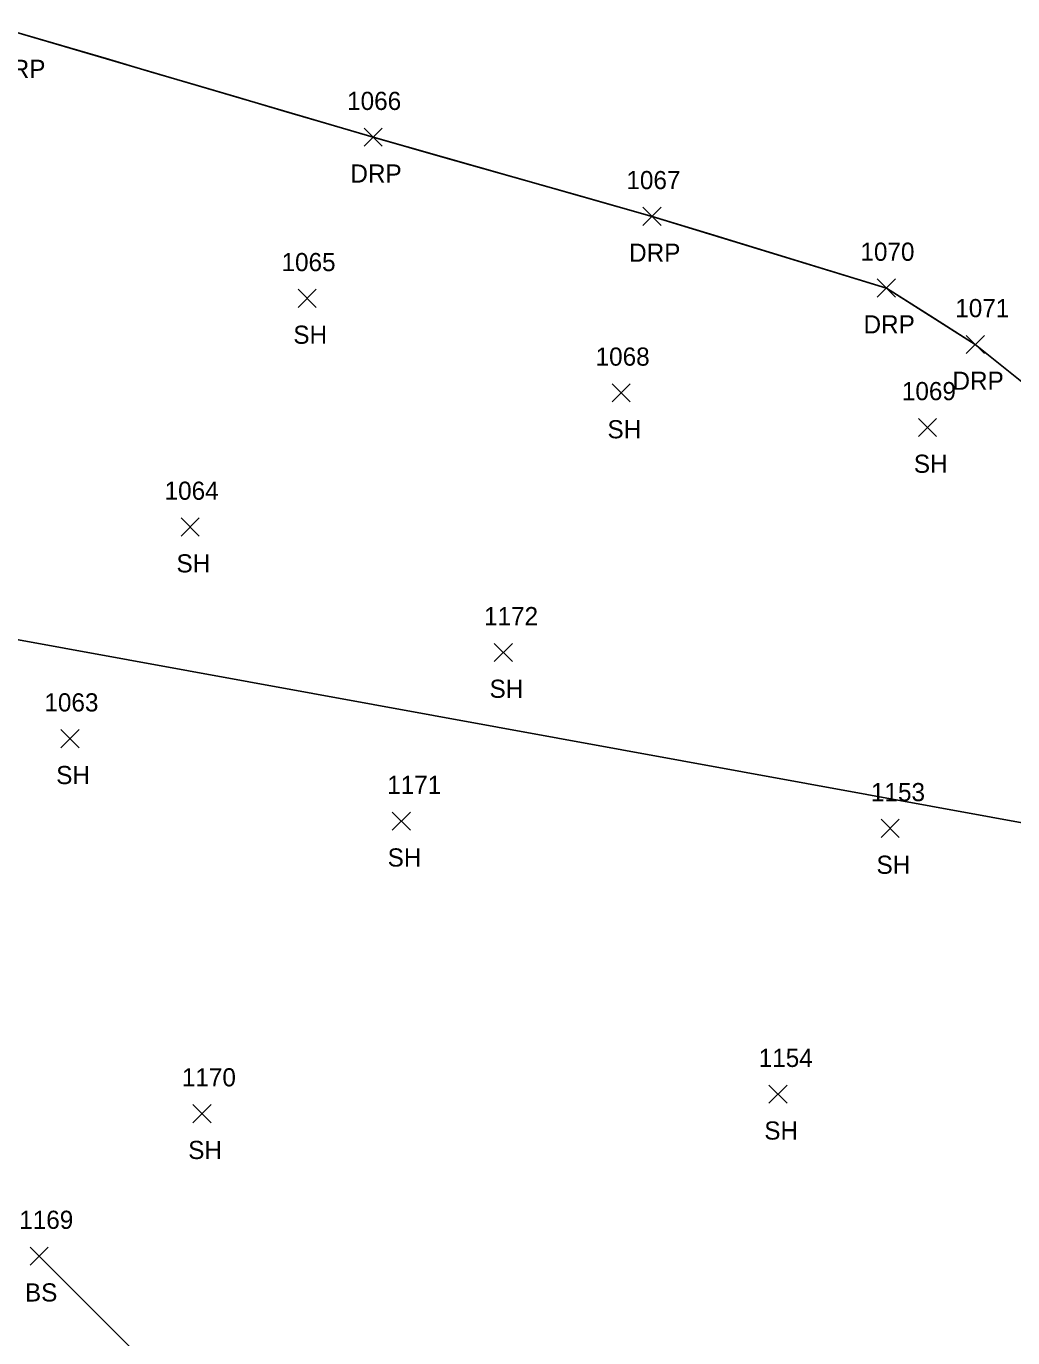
# Model space of a CAD drawing. Extents: x 1639430 to 1640195, y 612006 to 612917.
# Drawn here: x 1639980.2 to 1640088.8, y 612501.1 to 612645.5 of the extents above; entities that cross this region are included whole.
import ezdxf

# ---------------------------------------------------------------- set-up
doc = ezdxf.new("R2010")
doc.units = 0
for name, color, linetype in [('DCP', 7, 'Continuous'), ('L_A', 7, 'Continuous'), ('L_I', 7, 'Continuous'), ('L_TIC', 7, 'Continuous'), ('LELB', 7, 'Continuous'), ('LSOGP', 7, 'Continuous'), ('R_A', 7, 'Continuous'), ('R_I', 7, 'Continuous'), ('R_TIC', 7, 'Continuous'), ('RDP', 7, 'Continuous')]:
    doc.layers.add(name, color=color, linetype=linetype)

msp = doc.modelspace()

# ---------------------------------------------------------------- linework, layer by layer
at = {"layer": 'DCP'}
msp.add_lwpolyline([(1639875.64, 612596.85), (1640140.73, 612548.53)], dxfattribs=at)
at = {"layer": 'L_TIC'}
for points in [[(1640010.11, 612614.56), (1640012.11, 612616.56)], [(1640012.11, 612614.56), (1640010.11, 612616.56)], [(1640044.68, 612604.15), (1640046.68, 612606.15)], [(1640046.68, 612604.15), (1640044.68, 612606.15)], [(1640078.4, 612600.35), (1640080.4, 612602.35)], [(1640080.4, 612600.35), (1640078.4, 612602.35)], [(1639997.24, 612589.38), (1639999.24, 612591.38)], [(1639999.24, 612589.38), (1639997.24, 612591.38)], [(1640031.71, 612575.57), (1640033.71, 612577.57)], [(1640033.71, 612575.57), (1640031.71, 612577.57)], [(1639984.01, 612566.07), (1639986.01, 612568.07)], [(1639986.01, 612566.07), (1639984.01, 612568.07)], [(1640020.48, 612556.99), (1640022.48, 612558.99)], [(1640022.48, 612556.99), (1640020.48, 612558.99)], [(1640074.29, 612556.19), (1640076.29, 612558.19)], [(1640076.29, 612556.19), (1640074.29, 612558.19)], [(1640061.94, 612526.92), (1640063.94, 612528.92)], [(1640063.94, 612526.92), (1640061.94, 612528.92)], [(1639998.53, 612524.78), (1640000.53, 612526.78)], [(1640000.53, 612524.78), (1639998.53, 612526.78)], [(1639980.61, 612509.09), (1639982.61, 612511.09)], [(1639982.61, 612509.09), (1639980.61, 612511.09)]]:
    msp.add_lwpolyline(points, dxfattribs=at)
at = {"layer": 'LELB'}
msp.add_lwpolyline([(1640140.23, 612516.27), (1640123.47, 612499.22), (1640117.6, 612483.99), (1640116.42, 612461.14), (1640113.26, 612432.2), (1640089.7, 612438.66), (1640054.14, 612454.58), (1640026.5, 612472.2), (1639999.71, 612491.99), (1639981.61, 612510.09)], dxfattribs=at)
at = {"layer": 'LSOGP'}
msp.add_lwpolyline([(1640089.79, 612606.37), (1640084.65, 612610.49), (1640079.76, 612613.6), (1640074.87, 612616.7), (1640068.42, 612618.67), (1640061.97, 612620.64), (1640055.52, 612622.62), (1640049.07, 612624.59), (1640041.39, 612626.77), (1640033.72, 612628.95), (1640026.05, 612631.13), (1640018.38, 612633.31), (1640013.48, 612634.75), (1640008.58, 612636.19), (1640003.68, 612637.63), (1639998.78, 612639.07), (1639993.88, 612640.52), (1639988.98, 612641.96), (1639984.07, 612643.4), (1639979.17, 612644.84)], dxfattribs=at)
at = {"layer": 'R_TIC'}
for points in [[(1640017.38, 612632.31), (1640019.38, 612634.31)], [(1640019.38, 612632.31), (1640017.38, 612634.31)], [(1640048.07, 612623.59), (1640050.07, 612625.59)], [(1640050.07, 612623.59), (1640048.07, 612625.59)], [(1640073.87, 612615.7), (1640075.87, 612617.7)], [(1640075.87, 612615.7), (1640073.87, 612617.7)], [(1640083.65, 612609.49), (1640085.65, 612611.49)], [(1640085.65, 612609.49), (1640083.65, 612611.49)]]:
    msp.add_lwpolyline(points, dxfattribs=at)
at = {"layer": 'RDP'}
msp.add_lwpolyline([(1639965.19, 612645.53), (1639979.17, 612644.84), (1640018.38, 612633.31), (1640049.07, 612624.59), (1640074.87, 612616.7), (1640084.65, 612610.49), (1640094.93, 612602.25), (1640096.07, 612600.53), (1640095.84, 612598.58), (1640101.66, 612597.64), (1640108.13, 612607.66)], dxfattribs=at)

# ---------------------------------------------------------------- texts
at = {"layer": 'L_A'}
for s, p in [('SH', (1640009.59, 612610.56)), ('SH', (1640044.17, 612600.15)), ('SH', (1640077.89, 612596.35)), ('SH', (1639996.73, 612585.38)), ('SH', (1640031.19, 612571.57)), ('SH', (1639983.49, 612562.07)), ('SH', (1640019.97, 612552.99)), ('SH', (1640073.78, 612552.19)), ('SH', (1640061.43, 612522.92)), ('SH', (1639998.02, 612520.78)), ('BS', (1639980.05, 612505.09))]:
    msp.add_text(s, height=2, dxfattribs=at).set_placement(p)
at = {"layer": 'L_I'}
for s, p in [('1065', (1640008.29, 612618.56)), ('1068', (1640042.86, 612608.15)), ('1069', (1640076.57, 612604.35)), ('1064', (1639995.42, 612593.38)), ('1172', (1640030.58, 612579.57)), ('1063', (1639982.19, 612570.07)), ('1171', (1640019.92, 612560.99)), ('1153', (1640073.17, 612560.19)), ('1154', (1640060.81, 612530.92)), ('1170', (1639997.32, 612528.78)), ('1169', (1639979.42, 612513.09))]:
    msp.add_text(s, height=2, dxfattribs=at).set_placement(p)
at = {"layer": 'R_A'}
for p in [(1639976.66, 612639.84), (1640015.87, 612628.31), (1640046.55, 612619.59), (1640072.35, 612611.7), (1640082.14, 612605.49)]:
    msp.add_text('DRP', height=2, dxfattribs=at).set_placement(p)
at = {"layer": 'R_I'}
for s, p in [('1066', (1640015.51, 612636.31)), ('1067', (1640046.25, 612627.59)), ('1070', (1640072.01, 612619.7)), ('1071', (1640082.45, 612613.49))]:
    msp.add_text(s, height=2, dxfattribs=at).set_placement(p)

doc.saveas('drawing.dxf')
